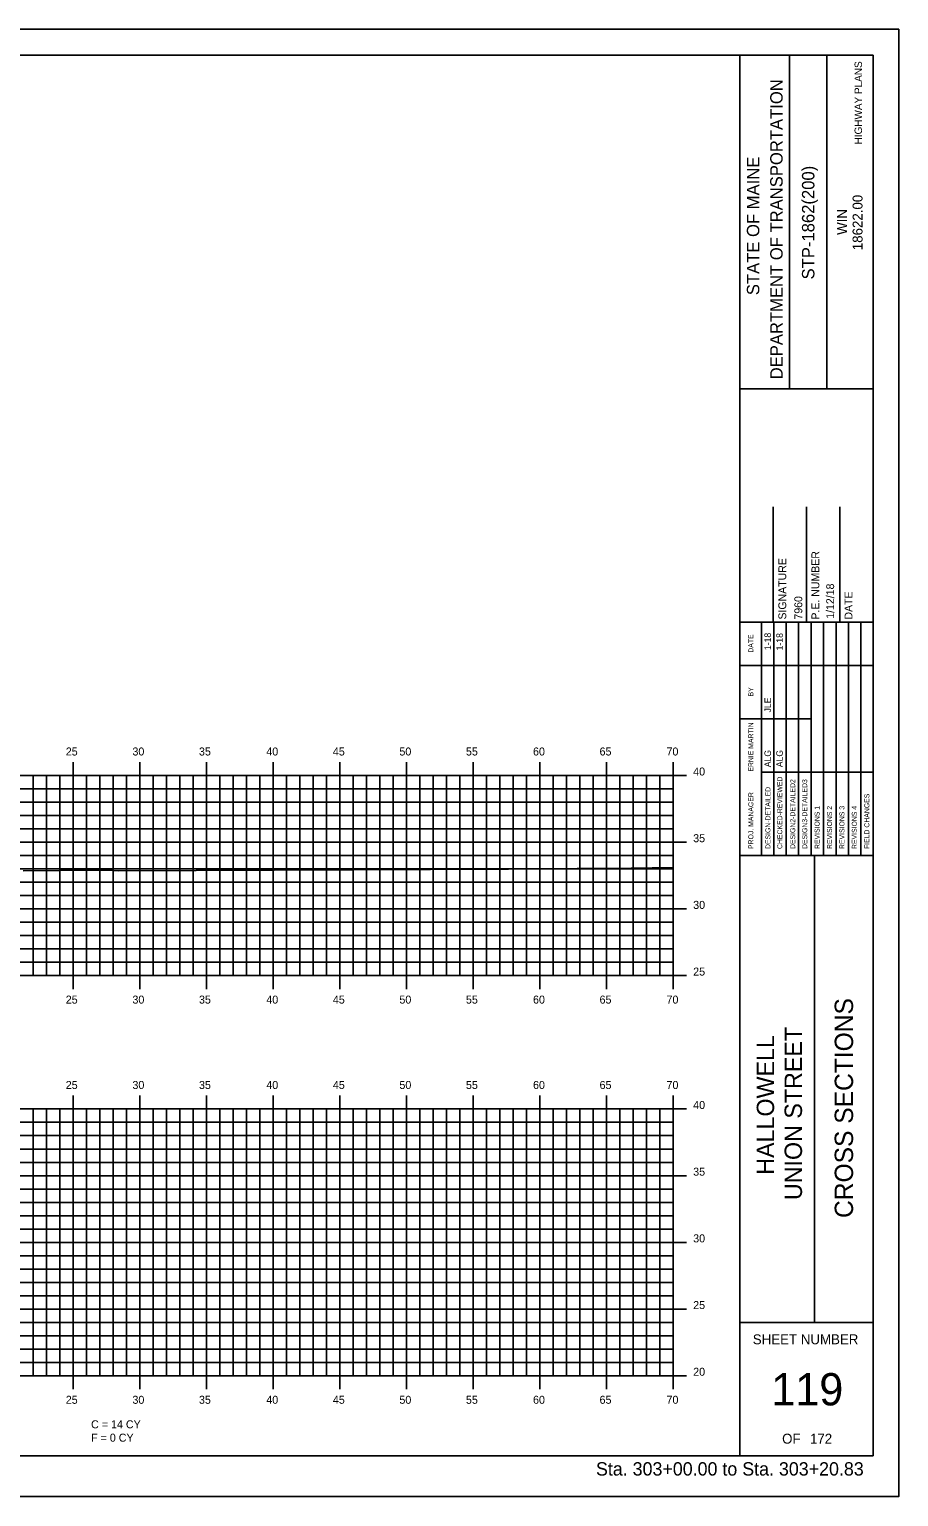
# Model space of a CAD drawing. Extents: x 1024350 to 1024520, y 394697 to 394807.
# Drawn here: x 1024454.7 to 1024519.9, y 394696.5 to 394806.5 of the extents above; entities that cross this region are included whole.
import ezdxf

# ---------------------------------------------------------------- set-up
doc = ezdxf.new("R2010")
doc.units = 0
for name, color, linetype in [('ANNOTATION', 7, 'Continuous'), ('BORDER', 7, 'Continuous'), ('H_V ANNOTATION', 7, 'Continuous'), ('HIGHWAY_TITLE', 7, 'Continuous'), ('MAJOR', 7, 'Continuous'), ('MINOR', 7, 'Continuous'), ('PLOT BOUNDARY', 7, 'Continuous'), ('S_Roadway_Centerline', 7, 'Continuous')]:
    doc.layers.add(name, color=color, linetype=linetype)

msp = doc.modelspace()

# ---------------------------------------------------------------- linework, layer by layer
at = {"layer": 'BORDER'}
for p, q in [((1024518, 394804.61), (1024358, 394804.61)), ((1024508, 394699.61), (1024508, 394804.61)), ((1024511.73, 394779.6), (1024511.73, 394804.6)), ((1024514.53, 394779.6), (1024514.53, 394804.6)), ((1024518, 394699.61), (1024518, 394804.61)), ((1024508, 394779.6), (1024518, 394779.6)), ((1024510.5, 394762.11), (1024510.5, 394770.76)), ((1024513, 394762.11), (1024513, 394770.76)), ((1024515.5, 394762.11), (1024515.5, 394770.76)), ((1024508, 394762.11), (1024518, 394762.11)), ((1024508, 394744.61), (1024518, 394744.61)), ((1024513.59, 394709.61), (1024513.59, 394744.61)), ((1024508, 394709.61), (1024518, 394709.61)), ((1024358, 394699.61), (1024518, 394699.61))]:
    msp.add_line(p, q, dxfattribs=at)
for points in [[(1024509.62, 394758.86), (1024509.62, 394762.11)], [(1024509.62, 394744.61), (1024509.62, 394761.4)], [(1024510.55, 394744.61), (1024510.55, 394762.11)], [(1024511.48, 394762.11), (1024511.48, 394744.61)], [(1024512.41, 394744.61), (1024512.41, 394762.11)], [(1024513.34, 394744.61), (1024513.34, 394762.11)], [(1024514.28, 394744.61), (1024514.28, 394762.11)], [(1024515.21, 394744.61), (1024515.21, 394762.11)], [(1024516.14, 394744.61), (1024516.14, 394762.11)], [(1024517.07, 394744.61), (1024517.07, 394762.11)], [(1024508, 394758.86), (1024518, 394758.86)], [(1024508, 394754.86), (1024509.62, 394754.86)], [(1024509.62, 394754.86), (1024513.34, 394754.86)], [(1024509.62, 394750.86), (1024518, 394750.86)]]:
    msp.add_lwpolyline(points, dxfattribs=at)
at = {"layer": 'MAJOR'}
for p, q in [((1024458, 394751.61), (1024458, 394750.61)), ((1024463, 394751.61), (1024463, 394750.61)), ((1024468, 394751.61), (1024468, 394750.61)), ((1024473, 394751.61), (1024473, 394750.61)), ((1024478, 394751.61), (1024478, 394750.61)), ((1024483, 394751.61), (1024483, 394750.61)), ((1024488, 394751.61), (1024488, 394750.61)), ((1024493, 394751.61), (1024493, 394750.61)), ((1024498, 394751.61), (1024498, 394750.61)), ((1024503, 394751.61), (1024503, 394750.61)), ((1024363, 394750.61), (1024503, 394750.61)), ((1024458, 394735.61), (1024458, 394750.61)), ((1024463, 394735.61), (1024463, 394750.61)), ((1024468, 394735.61), (1024468, 394750.61)), ((1024473, 394735.61), (1024473, 394750.61)), ((1024478, 394735.61), (1024478, 394750.61)), ((1024483, 394735.61), (1024483, 394750.61)), ((1024488, 394735.61), (1024488, 394750.61)), ((1024493, 394735.61), (1024493, 394750.61)), ((1024498, 394735.61), (1024498, 394750.61)), ((1024504, 394750.61), (1024502, 394750.61)), ((1024503, 394735.61), (1024503, 394750.61)), ((1024363, 394745.61), (1024503, 394745.61)), ((1024504, 394745.61), (1024502, 394745.61)), ((1024363, 394740.61), (1024503, 394740.61)), ((1024504, 394740.61), (1024502, 394740.61)), ((1024363, 394735.61), (1024503, 394735.61)), ((1024458, 394734.6), (1024458, 394735.61)), ((1024463, 394734.6), (1024463, 394735.61)), ((1024468, 394734.6), (1024468, 394735.61)), ((1024473, 394734.6), (1024473, 394735.61)), ((1024478, 394734.6), (1024478, 394735.61)), ((1024483, 394734.6), (1024483, 394735.61)), ((1024488, 394734.6), (1024488, 394735.61)), ((1024493, 394734.6), (1024493, 394735.61)), ((1024498, 394734.6), (1024498, 394735.61)), ((1024504, 394735.61), (1024502, 394735.61)), ((1024503, 394734.6), (1024503, 394735.61)), ((1024458, 394726.61), (1024458, 394725.61)), ((1024463, 394726.61), (1024463, 394725.61)), ((1024468, 394726.61), (1024468, 394725.61)), ((1024473, 394726.61), (1024473, 394725.61)), ((1024478, 394726.61), (1024478, 394725.61)), ((1024483, 394726.61), (1024483, 394725.61)), ((1024488, 394726.61), (1024488, 394725.61)), ((1024493, 394726.61), (1024493, 394725.61)), ((1024498, 394726.61), (1024498, 394725.61)), ((1024503, 394726.61), (1024503, 394725.61)), ((1024363, 394725.61), (1024503, 394725.61)), ((1024458, 394705.61), (1024458, 394725.61)), ((1024463, 394705.61), (1024463, 394725.61)), ((1024468, 394705.61), (1024468, 394725.61)), ((1024473, 394705.61), (1024473, 394725.61)), ((1024478, 394705.61), (1024478, 394725.61)), ((1024483, 394705.61), (1024483, 394725.61)), ((1024488, 394705.61), (1024488, 394725.61)), ((1024493, 394705.61), (1024493, 394725.61)), ((1024498, 394705.61), (1024498, 394725.61)), ((1024504, 394725.61), (1024502, 394725.61)), ((1024503, 394705.61), (1024503, 394725.61)), ((1024363, 394720.61), (1024503, 394720.61)), ((1024504, 394720.61), (1024502, 394720.61)), ((1024363, 394715.61), (1024503, 394715.61)), ((1024504, 394715.61), (1024502, 394715.61)), ((1024363, 394710.61), (1024503, 394710.61)), ((1024504, 394710.61), (1024502, 394710.61)), ((1024363, 394705.61), (1024503, 394705.61)), ((1024458, 394704.6), (1024458, 394705.61)), ((1024463, 394704.6), (1024463, 394705.61)), ((1024468, 394704.6), (1024468, 394705.61)), ((1024473, 394704.6), (1024473, 394705.61)), ((1024478, 394704.6), (1024478, 394705.61)), ((1024483, 394704.6), (1024483, 394705.61)), ((1024488, 394704.6), (1024488, 394705.61)), ((1024493, 394704.6), (1024493, 394705.61)), ((1024498, 394704.6), (1024498, 394705.61)), ((1024504, 394705.61), (1024502, 394705.61)), ((1024503, 394704.6), (1024503, 394705.61))]:
    msp.add_line(p, q, dxfattribs=at)
at = {"layer": 'MINOR'}
for p, q in [((1024455, 394735.61), (1024455, 394750.61)), ((1024456, 394735.61), (1024456, 394750.61)), ((1024457, 394735.61), (1024457, 394750.61)), ((1024459, 394735.61), (1024459, 394750.61)), ((1024460, 394735.61), (1024460, 394750.61)), ((1024461, 394735.61), (1024461, 394750.61)), ((1024462, 394735.61), (1024462, 394750.61)), ((1024464, 394735.61), (1024464, 394750.61)), ((1024465, 394735.61), (1024465, 394750.61)), ((1024466, 394735.61), (1024466, 394750.61)), ((1024467, 394735.61), (1024467, 394750.61)), ((1024469, 394735.61), (1024469, 394750.61)), ((1024470, 394735.61), (1024470, 394750.61)), ((1024471, 394735.61), (1024471, 394750.61)), ((1024472, 394735.61), (1024472, 394750.61)), ((1024474, 394735.61), (1024474, 394750.61)), ((1024475, 394735.61), (1024475, 394750.61)), ((1024476, 394735.61), (1024476, 394750.61)), ((1024477, 394735.61), (1024477, 394750.61)), ((1024479, 394735.61), (1024479, 394750.61)), ((1024480, 394735.61), (1024480, 394750.61)), ((1024481, 394735.61), (1024481, 394750.61)), ((1024482, 394735.61), (1024482, 394750.61)), ((1024484, 394735.61), (1024484, 394750.61)), ((1024485, 394735.61), (1024485, 394750.61)), ((1024486, 394735.61), (1024486, 394750.61)), ((1024487, 394735.61), (1024487, 394750.61)), ((1024489, 394735.61), (1024489, 394750.61)), ((1024490, 394735.61), (1024490, 394750.61)), ((1024491, 394735.61), (1024491, 394750.61)), ((1024492, 394735.61), (1024492, 394750.61)), ((1024494, 394735.61), (1024494, 394750.61)), ((1024495, 394735.61), (1024495, 394750.61)), ((1024496, 394735.61), (1024496, 394750.61)), ((1024497, 394735.61), (1024497, 394750.61)), ((1024499, 394735.61), (1024499, 394750.61)), ((1024500, 394735.61), (1024500, 394750.61)), ((1024501, 394735.61), (1024501, 394750.61)), ((1024502, 394735.61), (1024502, 394750.61)), ((1024363, 394749.61), (1024503, 394749.61)), ((1024503, 394749.61), (1024502, 394749.61)), ((1024363, 394748.61), (1024503, 394748.61)), ((1024503, 394748.61), (1024502, 394748.61)), ((1024363, 394747.61), (1024503, 394747.61)), ((1024503, 394747.61), (1024502, 394747.61)), ((1024363, 394746.61), (1024503, 394746.61)), ((1024503, 394746.61), (1024502, 394746.61)), ((1024363, 394744.61), (1024503, 394744.61)), ((1024503, 394744.61), (1024502, 394744.61)), ((1024363, 394743.61), (1024503, 394743.61)), ((1024503, 394743.61), (1024502, 394743.61)), ((1024363, 394742.61), (1024503, 394742.61)), ((1024363, 394741.61), (1024503, 394741.61)), ((1024503, 394742.61), (1024502, 394742.61)), ((1024503, 394741.61), (1024502, 394741.61)), ((1024363, 394739.61), (1024503, 394739.61)), ((1024503, 394739.61), (1024502, 394739.61)), ((1024363, 394738.61), (1024503, 394738.61)), ((1024503, 394738.61), (1024502, 394738.61)), ((1024363, 394737.61), (1024503, 394737.61)), ((1024503, 394737.61), (1024502, 394737.61)), ((1024363, 394736.61), (1024503, 394736.61)), ((1024503, 394736.61), (1024502, 394736.61)), ((1024455, 394705.61), (1024455, 394725.61)), ((1024456, 394705.61), (1024456, 394725.61)), ((1024457, 394705.61), (1024457, 394725.61)), ((1024459, 394705.61), (1024459, 394725.61)), ((1024460, 394705.61), (1024460, 394725.61)), ((1024461, 394705.61), (1024461, 394725.61)), ((1024462, 394705.61), (1024462, 394725.61)), ((1024464, 394705.61), (1024464, 394725.61)), ((1024465, 394705.61), (1024465, 394725.61)), ((1024466, 394705.61), (1024466, 394725.61)), ((1024467, 394705.61), (1024467, 394725.61)), ((1024469, 394705.61), (1024469, 394725.61)), ((1024470, 394705.61), (1024470, 394725.61)), ((1024471, 394705.61), (1024471, 394725.61)), ((1024472, 394705.61), (1024472, 394725.61)), ((1024474, 394705.61), (1024474, 394725.61)), ((1024475, 394705.61), (1024475, 394725.61)), ((1024476, 394705.61), (1024476, 394725.61)), ((1024477, 394705.61), (1024477, 394725.61)), ((1024479, 394705.61), (1024479, 394725.61)), ((1024480, 394705.61), (1024480, 394725.61)), ((1024481, 394705.61), (1024481, 394725.61)), ((1024482, 394705.61), (1024482, 394725.61)), ((1024484, 394705.61), (1024484, 394725.61)), ((1024485, 394705.61), (1024485, 394725.61)), ((1024486, 394705.61), (1024486, 394725.61)), ((1024487, 394705.61), (1024487, 394725.61)), ((1024489, 394705.61), (1024489, 394725.61)), ((1024490, 394705.61), (1024490, 394725.61)), ((1024491, 394705.61), (1024491, 394725.61)), ((1024492, 394705.61), (1024492, 394725.61)), ((1024494, 394705.61), (1024494, 394725.61)), ((1024495, 394705.61), (1024495, 394725.61)), ((1024496, 394705.61), (1024496, 394725.61)), ((1024497, 394705.61), (1024497, 394725.61)), ((1024499, 394705.61), (1024499, 394725.61)), ((1024500, 394705.61), (1024500, 394725.61)), ((1024501, 394705.61), (1024501, 394725.61)), ((1024502, 394705.61), (1024502, 394725.61)), ((1024363, 394724.61), (1024503, 394724.61)), ((1024503, 394724.61), (1024502, 394724.61)), ((1024363, 394723.61), (1024503, 394723.61)), ((1024503, 394723.61), (1024502, 394723.61)), ((1024363, 394722.61), (1024503, 394722.61)), ((1024503, 394722.61), (1024502, 394722.61)), ((1024363, 394721.61), (1024503, 394721.61)), ((1024503, 394721.61), (1024502, 394721.61)), ((1024363, 394719.61), (1024503, 394719.61)), ((1024503, 394719.61), (1024502, 394719.61)), ((1024363, 394718.61), (1024503, 394718.61)), ((1024503, 394718.61), (1024502, 394718.61)), ((1024363, 394717.61), (1024503, 394717.61)), ((1024503, 394717.61), (1024502, 394717.61)), ((1024363, 394716.61), (1024503, 394716.61)), ((1024503, 394716.61), (1024502, 394716.61)), ((1024363, 394714.61), (1024503, 394714.61)), ((1024503, 394714.61), (1024502, 394714.61)), ((1024363, 394713.61), (1024503, 394713.61)), ((1024503, 394713.61), (1024502, 394713.61)), ((1024363, 394712.61), (1024503, 394712.61)), ((1024503, 394712.61), (1024502, 394712.61)), ((1024363, 394711.61), (1024503, 394711.61)), ((1024503, 394711.61), (1024502, 394711.61)), ((1024363, 394709.61), (1024503, 394709.61)), ((1024363, 394708.61), (1024503, 394708.61)), ((1024503, 394709.61), (1024502, 394709.61)), ((1024503, 394708.61), (1024502, 394708.61)), ((1024363, 394707.61), (1024503, 394707.61)), ((1024503, 394707.61), (1024502, 394707.61)), ((1024363, 394706.61), (1024503, 394706.61)), ((1024503, 394706.61), (1024502, 394706.61))]:
    msp.add_line(p, q, dxfattribs=at)
at = {"layer": 'PLOT BOUNDARY'}
msp.add_lwpolyline([(1024349.91, 394696.55), (1024519.91, 394696.55), (1024519.91, 394806.55), (1024349.91, 394806.55)], close=True, dxfattribs=at)
at = {"layer": 'S_Roadway_Centerline'}
msp.add_lwpolyline([(1024454.26, 394743.47), (1024459.69, 394743.51), (1024459.96, 394743.51), (1024460.59, 394743.51), (1024461.39, 394743.47), (1024490.66, 394743.59), (1024491.1, 394743.61), (1024495.8, 394743.64), (1024499.86, 394743.67), (1024503, 394743.71)], dxfattribs=at)

# ---------------------------------------------------------------- texts
at = {"layer": 'ANNOTATION'}
for s, p in [('C = 14 CY', (1024459.35, 394701.67)), ('F = 0 CY', (1024459.35, 394700.67))]:
    msp.add_text(s, height=0.6, dxfattribs=at).set_placement(p)
at = {"layer": 'BORDER'}
for s, height, rotation, p in [('DEPARTMENT OF TRANSPORTATION', 0.9318, 90, (1024511.21, 394780.31)), ('STATE OF MAINE', 0.9318, 90, (1024509.46, 394786.62)), ('STP-1862(200)', 0.9318, 90, (1024513.59, 394787.8)), ('18622.00', 0.745, 90, (1024517.2, 394789.99)), ('WIN', 0.745, 90, (1024516.04, 394791.14)), ('P.E. NUMBER', 0.5906, 90, (1024513.96, 394762.3)), ('SIGNATURE', 0.591, 90, (1024511.48, 394762.3)), ('1/12/18', 0.591, 90, (1024515.07, 394762.36)), ('7960', 0.591, 90, (1024512.68, 394762.3)), ('DATE', 0.591, 90, (1024516.44, 394762.3)), ('DATE', 0.371, 90, (1024509.01, 394759.82)), ('1-18', 0.485, 90, (1024510.33, 394760.01)), ('1-18', 0.485, 90, (1024511.22, 394759.99)), ('BY', 0.371, 90, (1024509.01, 394756.54)), ('JLE', 0.485, 90, (1024510.33, 394755.34)), ('ERNIE MARTIN', 0.3727, 90, (1024509.01, 394750.9)), ('ALG', 0.485, 90, (1024510.33, 394751.23)), ('ALG', 0.485, 90, (1024511.22, 394751.23)), ('DESIGN-DETAILED', 0.3727, 90, (1024510.29, 394745.1)), ('CHECKED-REVIEWED', 0.3727, 90, (1024511.18, 394745.1)), ('DESIGN2-DETAILED2', 0.3727, 90, (1024512.15, 394745.1)), ('DESIGN3-DETAILED3', 0.3727, 90, (1024513.05, 394745.1)), ('PROJ. MANAGER', 0.3727, 90, (1024509.01, 394745.1)), ('REVISIONS 1', 0.3727, 90, (1024513.98, 394745.1)), ('REVISIONS 2', 0.3727, 90, (1024514.91, 394745.1)), ('REVISIONS 3', 0.3727, 90, (1024515.84, 394745.1)), ('REVISIONS 4', 0.3727, 90, (1024516.77, 394745.1)), ('FIELD CHANGES', 0.3727, 90, (1024517.71, 394745.1)), ('CROSS SECTIONS', 1.3779, 90, (1024516.49, 394717.44)), ('SHEET NUMBER', 0.7453, 360, (1024508.97, 394707.97)), ('119', 2.419, 360, (1024510.36, 394703.39)), ('OF', 0.745, 360, (1024511.17, 394700.52)), ('172', 0.745, 360, (1024513.26, 394700.52))]:
    msp.add_text(s, height=height, rotation=rotation, dxfattribs=at).set_placement(p)
at = {"layer": 'H_V ANNOTATION'}
for s, height, p in [('25', 0.6, (1024457.45, 394752.11)), ('30', 0.6, (1024462.45, 394752.11)), ('35', 0.6, (1024467.44, 394752.11)), ('40', 0.6, (1024472.49, 394752.11)), ('45', 0.6, (1024477.48, 394752.11)), ('50', 0.6, (1024482.47, 394752.11)), ('55', 0.6, (1024487.46, 394752.11)), ('60', 0.6, (1024492.49, 394752.11)), ('65', 0.6, (1024497.48, 394752.11)), ('70', 0.6, (1024502.5, 394752.11)), ('40', 0.6, (1024504.5, 394750.61)), ('35', 0.6, (1024504.5, 394745.61)), ('30', 0.6, (1024504.5, 394740.61)), ('25', 0.6, (1024504.5, 394735.61)), ('25', 0.6, (1024457.45, 394733.51)), ('30', 0.6, (1024462.45, 394733.51)), ('35', 0.6, (1024467.44, 394733.51)), ('40', 0.6, (1024472.49, 394733.51)), ('45', 0.6, (1024477.48, 394733.51)), ('50', 0.6, (1024482.47, 394733.51)), ('55', 0.6, (1024487.46, 394733.51)), ('60', 0.6, (1024492.49, 394733.51)), ('65', 0.6, (1024497.48, 394733.51)), ('70', 0.6, (1024502.5, 394733.51)), ('25', 0.6, (1024457.45, 394727.11)), ('30', 0.6, (1024462.45, 394727.11)), ('35', 0.6, (1024467.44, 394727.11)), ('40', 0.6, (1024472.49, 394727.11)), ('45', 0.6, (1024477.48, 394727.11)), ('50', 0.6, (1024482.47, 394727.11)), ('55', 0.6, (1024487.46, 394727.11)), ('60', 0.6, (1024492.49, 394727.11)), ('65', 0.6, (1024497.48, 394727.11)), ('70', 0.6, (1024502.5, 394727.11)), ('40', 0.6, (1024504.5, 394725.61)), ('35', 0.6, (1024504.5, 394720.61)), ('30', 0.6, (1024504.5, 394715.61)), ('25', 0.6, (1024504.5, 394710.61)), ('20', 0.6, (1024504.5, 394705.61)), ('25', 0.6, (1024457.45, 394703.51)), ('30', 0.6, (1024462.45, 394703.51)), ('35', 0.6, (1024467.44, 394703.51)), ('40', 0.6, (1024472.49, 394703.51)), ('45', 0.6, (1024477.48, 394703.51)), ('50', 0.6, (1024482.47, 394703.51)), ('55', 0.6, (1024487.46, 394703.51)), ('60', 0.6, (1024492.49, 394703.51)), ('65', 0.6, (1024497.48, 394703.51)), ('70', 0.6, (1024502.5, 394703.51)), ('Sta. 303+00.00 to Sta. 303+20.83', 1.0002, (1024497.21, 394698.13))]:
    msp.add_text(s, height=height, dxfattribs=at).set_placement(p)
at = {"layer": 'HIGHWAY_TITLE'}
for s, height, p in [('HIGHWAY PLANS', 0.559, (1024517.16, 394797.92)), ('UNION STREET', 1.3043, (1024512.66, 394718.78)), ('HALLOWELL', 1.304, (1024510.57, 394720.68))]:
    msp.add_text(s, height=height, rotation=90, dxfattribs=at).set_placement(p)

doc.saveas('drawing.dxf')
